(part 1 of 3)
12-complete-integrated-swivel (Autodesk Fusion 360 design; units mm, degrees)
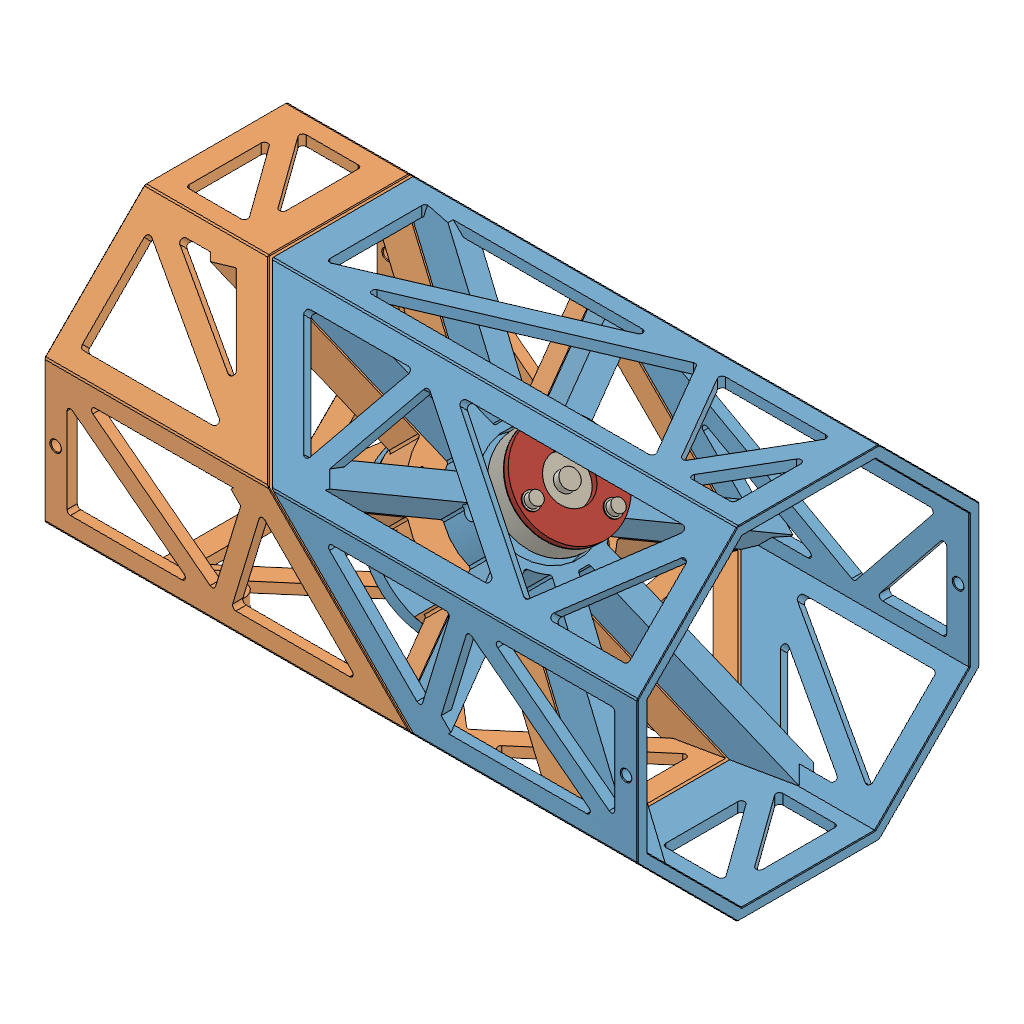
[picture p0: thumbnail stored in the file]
part number: 2026-11-02-20-17-55-344
part number: 2026-11-02-20-17-59-218
part number: 2026-11-02-20-17-59-224
part number: 2026-11-02-20-19-00-695
part number: 2026-11-02-20-19-03-009
part number: 2026-11-02-20-19-04-949
part number: 2026-11-02-20-19-06-912
part number: 2026-11-02-20-19-11-903
part number: 2026-11-02-20-19-12-666
part number: 2026-11-02-20-19-12-978
part number: 2026-11-02-20-19-13-740
part number: 2026-11-02-20-19-14-532
part number: 2026-11-02-20-19-15-361
part number: 2026-11-02-20-19-17-468
part number: 2026-11-02-20-19-19-583
part number: 2026-11-02-20-19-25-638
part number: 2026-11-02-20-19-39-091
parameter "bodyWidth" = 150 comment "Regular octagon across flats; corner diameter is larger."
parameter "bodyLength" = 260 comment "Overall straight length of the shared master blank."
parameter "splitAngle" = 45 comment "Keep this lesson angle at45 degrees."
parameter "faceGap" = 1 comment "Gap between the two printed joint faces."
parameter "wall" = 4.5 comment "Integrated shell and side brace radial thickness."
parameter "faceHalfWidth" = 31.066 (= "bodyWidth * ( sqrt(2) - 1 ) / 2") comment "Half-width of each outer planar facet."
parameter "memberWidth" = 8 comment "Nominal brace and corner chord width in a facet."
parameter "nodeHalfWidth" = 27.066 (= "faceHalfWidth - memberWidth / 2") comment "Chord centerlines measured from facet center."
parameter "jointNodeQ" = 7 comment "First truss skeleton row from the center joint plane."
parameter "endRim" = 10 comment "Uncut axial rim at each distant end."
parameter "endNodeX" = 124 (= "bodyLength / 2 - endRim + memberWidth / 2") comment "Last skeleton row before aperture inset."
parameter "apertureRadius" = 1.5 comment "Rounded internal corners at triangular openings."
parameter "spokeWidth" = 10 comment "Width of each deep bearing bulkhead spoke."
parameter "spokeDepth" = 18 comment "Bulkhead depth normal to the diagonal joint face."
parameter "carrierOD" = 52 comment "Outside of integrated A front bearing carrier."
parameter "rearCarrierClearance" = 46 comment "Internal carrier relief above front bearing shoulder."
parameter "tubeCornerChamfer" = 0.5 comment "Exposed outside octagon corner bevel."
parameter "tubeRimChamfer" = 0.3 comment "End rim and print-contact edge relief."
parameter "cordStation" = 125 (= "bodyLength / 2 - endRim / 2") comment "Load-test cord port center measured along body X."
parameter "bearingOD" = 22 comment "608 measured outside diameter."
parameter "bearingID" = 8 comment "608 bore."
parameter "bearingWidth" = 7 comment "608 width."
parameter "seatAllowance" = 0.2 comment "Trial DIAMETRAL clearance; choose with printed coupon."
parameter "seatDiameter" = 22.2 (= "bearingOD + seatAllowance") comment "Measured fit controls this."
parameter "coreOD" = 44 comment "Bearing holder outer diameter."
parameter "raceRelief" = 19.5 comment "Outer-ring shoulder opening; verify seals."
parameter "frontSeatDepth" = 7.1 comment "0.1 mm outer-ring axial allowance."
parameter "rearSeatDepth" = 7.2 comment "0.2 mm outer-ring axial float."
parameter "shoulder" = 3 comment "Backing behind each bearing seat."
parameter "supportSpacer" = 12 comment "Purchased metal M3 spacer length."
parameter "supportCircle" = 34 comment "Three M3 support bolts."
parameter "supportSpacerOD" = 6 comment "Purchased spacer outside diameter."
parameter "capThickness" = 3 comment "Both printed outer-ring retaining caps."
parameter "m3Clearance" = 3.3 comment "M3 through holes."
parameter "m4Clearance" = 4.3 comment "M4 through holes."
parameter "qFront" = 0.5 (= "faceGap / 2") comment "Front bearing starts at A mating face."
parameter "qFrontBack" = 10.6 (= "qFront + frontSeatDepth + shoulder") comment "End of integrated A holder."
parameter "qRearBase" = 22.6 (= "qFrontBack + supportSpacer") comment "Start of removable rear holder."
parameter "qRearBearing" = 25.6 (= "qRearBase + shoulder") comment "Rear bearing inner end."
parameter "qRearEnd" = 32.8 (= "qRearBearing + rearSeatDepth") comment "Rear holder outer end."
parameter "bearingSpacing" = 25.1 (= "qRearBearing - qFront") comment "Derived support-center spacing, not a bearing rating."
parameter "mountOD" = 76 comment "B mount and F flange outside diameter."
parameter "mountCircle" = 64 comment "Four M4 attachment holes."
parameter "mountOpening" = 50.3 comment "B through opening."
parameter "hubFace" = -23 comment "Metal hub flat mounting face."
parameter "adapterThickness" = 6 comment "F flange and metal compression sleeve length."
parameter "pilotDiameter" = 50 comment "F shallow centering pilot."
parameter "pilotInside" = 34 comment "Clearance around metal hub."
parameter "pilotHeight" = 2 comment "Short pilot only."
parameter "hubHoleSpacing" = 16 comment "Metal Sonic hub square hole spacing."
parameter "sleeveOD" = 8 comment "M4 metal compression sleeves."
parameter "sleeveAllowance" = 0.2 comment "Trial DIAMETRAL sleeve clearance."
parameter "shaftClearance" = 8.5 comment "F clearance hole; not a bearing."
parameter "nutAF" = 7.2 comment "M4 nominal 7 AF nut trial pocket."
parameter "nutDepth" = 4 comment "Open front M4 nut pocket."
parameter "rootRadius" = 1 comment "Hub-to-wall blend."
parameter "entryChamfer" = 0.4 comment "Assembly lead-in."
parameter "bedRelief" = 0.3 comment "Bed-contact edge allowance."
parameter "driverPort" = 5 comment "Clearance for bare3 mm hex-key shafts; bulky bit holders do not fit."
parameter "accessPadWidth" = 12 comment "Reinforced access-port capsule width."
parameter "accessPadExtra" = 2 comment "Local inward reinforcement beyond nominal side wall."
sketch "01 Master Octagon" plane through (0, 0, 0) normal (1, 0, 0) x axis (0, 0, -1)
  line L1 (31.066, 75) -> (75, 31.066)
  line L2 (-31.066, 75) -> (31.066, 75)
  line L3 (-75, 31.066) -> (-31.066, 75)
  line L4 (-75, -31.066) -> (-75, 31.066)
  line L5 (-31.066, -75) -> (-75, -31.066)
  line L6 (31.066, -75) -> (-31.066, -75)
  line L7 (75, -31.066) -> (31.066, -75)
  line L8 (75, 31.066) -> (75, -31.066)
  point P1 (0, 0)
  point P10 (0, 0)
  point P3 (31.066, 75)
  point P8 (31.066, -75)
  coincident P1 P10
  horizontal L2
  dimension "d59" distance P3 P8 = 150 (= "bodyWidth")
extrude "Extrude1" new body sketch "01 Master Octagon" distance 260 (= "bodyLength")
work_plane "WorkPlane1" RotateAngle 45 (= "splitAngle") ExtraOffset 0
split "Split1"
offset_faces "OffsetFaces1" distance -0.5 (= "-faceGap / 2")
offset_faces "OffsetFaces2" distance -0.5 (= "-faceGap / 2")
component_from_bodies "Body->Comp1"
component_from_bodies "Body->Comp2"
shell "Shell1" innerThickness 4.5 (= "wall")
shell "Shell1" innerThickness 4.5 (= "wall")
work_plane "WorkPlane1" RotateAngle -90 ExtraOffset 0
work_plane "WorkPlane2" AlongDistance 75 (= "bodyWidth / 2") ExtraOffset 0
sketch "A Facet 0 Triangle 1" plane through (0, 75, 0) normal (0, 1, 0) x axis (1, 0, 0)
  line L1 (-65.1005, -27.066) -> (-65.1005, 27.066)
  line L2 (60.9665, 27.066) -> (-65.1005, -27.066)
  line L3 (-65.1005, 27.066) -> (60.9665, 27.066)
  line L4 (-61.1005, -20.9953) -> (-61.1005, 23.066)
  line L5 (41.513, 23.066) -> (-61.1005, -20.9953)
  line L6 (-61.1005, 23.066) -> (41.513, 23.066)
  point P1 (0, 0)
  point P2 (-65.1005, 27.066)
  point P3 (-65.1005, -27.066)
  point P4 (60.9665, 27.066)
  dimension "d72" distance P1 P2 = 65.1005 (= "Linear Dimension-2")
  dimension "d73" distance P1 P2 = 27.066 (= "Linear Dimension-3")
  dimension "d74" distance P1 P3 = 65.1005 (= "Linear Dimension-4")
  dimension "d75" distance P1 P3 = 27.066 (= "Linear Dimension-5")
  dimension "d76" distance P1 P4 = 60.9665 (= "Linear Dimension-6")
  dimension "d77" distance P1 P4 = 27.066 (= "Linear Dimension-7")
  dimension "d78" = -4 (= "-memberWidth / 2")
extrude "Extrude1" cut sketch "A Facet 0 Triangle 1" profile of L5 L6 L4 against normal blind 4.7 (magnitude of "-( wall + 0.2 mm )")
sketch "A Facet 0 Triangle 2" plane through (0, 75, 0) normal (0, 1, 0) x axis (1, 0, 0)
  line L1 (60.9665, 27.066) -> (-65.1005, -27.066)
  line L2 (92.4832, -27.066) -> (60.9665, 27.066)
  line L3 (-65.1005, -27.066) -> (92.4832, -27.066)
  line L4 (59.2912, 21.9935) -> (-45.647, -23.066)
  line L5 (85.5258, -23.066) -> (59.2912, 21.9935)
  line L6 (-45.647, -23.066) -> (85.5258, -23.066)
  point P1 (0, 0)
  point P2 (-65.1005, -27.066)
  point P3 (60.9665, 27.066)
  point P4 (92.4832, -27.066)
  dimension "d81" distance P1 P2 = 65.1005 (= "Linear Dimension-2")
  dimension "d82" distance P1 P2 = 27.066 (= "Linear Dimension-3")
  dimension "d83" distance P1 P3 = 60.9665 (= "Linear Dimension-4")
  dimension "d84" distance P1 P3 = 27.066 (= "Linear Dimension-5")
  dimension "d85" distance P1 P4 = 92.4832 (= "Linear Dimension-6")
  dimension "d86" distance P1 P4 = 27.066 (= "Linear Dimension-7")
  dimension "d87" = 4 (= "memberWidth / 2")
extrude "Extrude2" cut sketch "A Facet 0 Triangle 2" profile of L5 L6 L4 against normal blind 4.7 (magnitude of "-( wall + 0.2 mm )")
sketch "A Facet 0 Triangle 3" plane through (0, 75, 0) normal (0, 1, 0) x axis (1, 0, 0)
  line L1 (92.4832, -27.066) -> (60.9665, 27.066)
  line L2 (124, 27.066) -> (92.4832, -27.066)
  line L3 (60.9665, 27.066) -> (124, 27.066)
  line L4 (92.4832, -19.1161) -> (67.924, 23.066)
  line L5 (117.0425, 23.066) -> (92.4832, -19.1161)
  line L6 (67.924, 23.066) -> (117.0425, 23.066)
  point P1 (0, 0)
  point P2 (60.9665, 27.066)
  point P3 (92.4832, -27.066)
  point P4 (124, 27.066)
  dimension "d90" distance P1 P2 = 60.9665 (= "Linear Dimension-2")
  dimension "d91" distance P1 P2 = 27.066 (= "Linear Dimension-3")
  dimension "d92" distance P1 P3 = 92.4832 (= "Linear Dimension-4")
  dimension "d93" distance P1 P3 = 27.066 (= "Linear Dimension-5")
  dimension "d94" distance P1 P4 = 124 (= "Linear Dimension-6")
  dimension "d95" distance P1 P4 = 27.066 (= "Linear Dimension-7")
  dimension "d96" = -4 (= "-memberWidth / 2")
extrude "Extrude3" cut sketch "A Facet 0 Triangle 3" profile of L5 L6 L4 against normal blind 4.7 (magnitude of "-( wall + 0.2 mm )")
sketch "A Facet 0 Triangle 4" plane through (0, 75, 0) normal (0, 1, 0) x axis (1, 0, 0)
  line L1 (124, 27.066) -> (92.4832, -27.066)
  line L2 (124, -27.066) -> (124, 27.066)
  line L3 (92.4832, -27.066) -> (124, -27.066)
  line L4 (120, 12.2459) -> (99.4407, -23.066)
  line L5 (120, -23.066) -> (120, 12.2459)
  line L6 (99.4407, -23.066) -> (120, -23.066)
  point P1 (0, 0)
  point P2 (92.4832, -27.066)
  point P3 (124, 27.066)
  point P4 (124, -27.066)
  dimension "d99" distance P1 P2 = 92.4832 (= "Linear Dimension-2")
  dimension "d100" distance P1 P2 = 27.066 (= "Linear Dimension-3")
  dimension "d101" distance P1 P3 = 124 (= "Linear Dimension-4")
  dimension "d102" distance P1 P3 = 27.066 (= "Linear Dimension-5")
  dimension "d103" distance P1 P4 = 124 (= "Linear Dimension-6")
  dimension "d104" distance P1 P4 = 27.066 (= "Linear Dimension-7")
  dimension "d105" = 4 (= "memberWidth / 2")
extrude "Extrude4" cut sketch "A Facet 0 Triangle 4" profile of L5 L6 L4 against normal blind 4.7 (magnitude of "-( wall + 0.2 mm )")
fillet "Fillet1" radius 1.5 (= "apertureRadius")
work_plane "WorkPlane3" RotateAngle -45 ExtraOffset 0
work_plane "WorkPlane4" AlongDistance 75 (= "bodyWidth / 2") ExtraOffset 0
sketch "A Facet 45 Triangle 1" plane through (0, 53.033, 53.033) normal (0, 0.7071, 0.7071) x axis (1, 0, 0)
  line L1 (-23.9949, -27.066) -> (-62.2721, 27.066)
  line L2 (-0.1814, 27.066) -> (-23.9949, -27.066)
  line L3 (-62.2721, 27.066) -> (-0.1814, 27.066)
  line L4 (-24.81, -18.9852) -> (-54.5447, 23.066)
  line L5 (-6.311, 23.066) -> (-24.81, -18.9852)
  line L6 (-54.5447, 23.066) -> (-6.311, 23.066)
  point P1 (0, 0)
  point P2 (-62.2721, 27.066)
  point P3 (-23.9949, -27.066)
  point P4 (-0.1814, 27.066)
  dimension "d114" distance P1 P2 = 62.2721 (= "Linear Dimension-2")
  dimension "d115" distance P1 P2 = 27.066 (= "Linear Dimension-3")
  dimension "d116" distance P1 P3 = 23.9949 (= "Linear Dimension-4")
  dimension "d117" distance P1 P3 = 27.066 (= "Linear Dimension-5")
  dimension "d118" distance P1 P4 = 0.1814 (= "Linear Dimension-6")
  dimension "d119" distance P1 P4 = 27.066 (= "Linear Dimension-7")
  dimension "d120" = -4 (= "-memberWidth / 2")
extrude "Extrude5" cut sketch "A Facet 45 Triangle 1" profile of L5 L6 L4 against normal blind 4.7 (magnitude of "-( wall + 0.2 mm )")
sketch "A Facet 45 Triangle 2" plane through (0, 53.033, 53.033) normal (0, 0.7071, 0.7071) x axis (1, 0, 0)
  line L1 (-0.1814, 27.066) -> (-23.9949, -27.066)
  line L2 (74.6684, -27.066) -> (-0.1814, 27.066)
  line L3 (-23.9949, -27.066) -> (74.6684, -27.066)
  line L4 (1.4863, 20.9235) -> (-17.8653, -23.066)
  line L5 (62.3117, -23.066) -> (1.4863, 20.9235)
  line L6 (-17.8653, -23.066) -> (62.3117, -23.066)
  point P1 (0, 0)
  point P2 (-23.9949, -27.066)
  point P3 (-0.1814, 27.066)
  point P4 (74.6684, -27.066)
  dimension "d123" distance P1 P2 = 23.9949 (= "Linear Dimension-2")
  dimension "d124" distance P1 P2 = 27.066 (= "Linear Dimension-3")
  dimension "d125" distance P1 P3 = 0.1814 (= "Linear Dimension-4")
  dimension "d126" distance P1 P3 = 27.066 (= "Linear Dimension-5")
  dimension "d127" distance P1 P4 = 74.6684 (= "Linear Dimension-6")
  dimension "d128" distance P1 P4 = 27.066 (= "Linear Dimension-7")
  dimension "d129" = 4 (= "memberWidth / 2")
extrude "Extrude6" cut sketch "A Facet 45 Triangle 2" profile of L5 L6 L4 against normal blind 4.7 (magnitude of "-( wall + 0.2 mm )")
sketch "A Facet 45 Triangle 3" plane through (0, 53.033, 53.033) normal (0, 0.7071, 0.7071) x axis (1, 0, 0)
  line L1 (74.6684, -27.066) -> (-0.1814, 27.066)
  line L2 (124, 27.066) -> (74.6684, -27.066)
  line L3 (-0.1814, 27.066) -> (124, 27.066)
  line L4 (74.1179, -21.7315) -> (12.1753, 23.066)
  line L5 (114.9429, 23.066) -> (74.1179, -21.7315)
  line L6 (12.1753, 23.066) -> (114.9429, 23.066)
  point P1 (0, 0)
  point P2 (-0.1814, 27.066)
  point P3 (74.6684, -27.066)
  point P4 (124, 27.066)
  dimension "d132" distance P1 P2 = 0.1814 (= "Linear Dimension-2")
  dimension "d133" distance P1 P2 = 27.066 (= "Linear Dimension-3")
  dimension "d134" distance P1 P3 = 74.6684 (= "Linear Dimension-4")
  dimension "d135" distance P1 P3 = 27.066 (= "Linear Dimension-5")
  dimension "d136" distance P1 P4 = 124 (= "Linear Dimension-6")
  dimension "d137" distance P1 P4 = 27.066 (= "Linear Dimension-7")
  dimension "d138" = -4 (= "-memberWidth / 2")
extrude "Extrude7" cut sketch "A Facet 45 Triangle 3" profile of L5 L6 L4 against normal blind 4.7 (magnitude of "-( wall + 0.2 mm )")
sketch "A Facet 45 Triangle 4" plane through (0, 53.033, 53.033) normal (0, 0.7071, 0.7071) x axis (1, 0, 0)
  line L1 (124, 27.066) -> (74.6684, -27.066)
  line L2 (124, -27.066) -> (124, 27.066)
  line L3 (74.6684, -27.066) -> (124, -27.066)
  line L4 (120, 16.7383) -> (83.7255, -23.066)
  line L5 (120, -23.066) -> (120, 16.7383)
  line L6 (83.7255, -23.066) -> (120, -23.066)
  point P1 (0, 0)
  point P2 (74.6684, -27.066)
  point P3 (124, 27.066)
  point P4 (124, -27.066)
  dimension "d141" distance P1 P2 = 74.6684 (= "Linear Dimension-2")
  dimension "d142" distance P1 P2 = 27.066 (= "Linear Dimension-3")
  dimension "d143" distance P1 P3 = 124 (= "Linear Dimension-4")
  dimension "d144" distance P1 P3 = 27.066 (= "Linear Dimension-5")
  dimension "d145" distance P1 P4 = 124 (= "Linear Dimension-6")
  dimension "d146" distance P1 P4 = 27.066 (= "Linear Dimension-7")
  dimension "d147" = 4 (= "memberWidth / 2")
extrude "Extrude8" cut sketch "A Facet 45 Triangle 4" profile of L5 L6 L4 against normal blind 4.7 (magnitude of "-( wall + 0.2 mm )")
fillet "Fillet2" radius 1.5 (= "apertureRadius")
work_plane "WorkPlane5" RotateAngle 0 ExtraOffset 0
work_plane "WorkPlane6" AlongDistance 75 (= "bodyWidth / 2") ExtraOffset 0
sketch "A Facet 90 Triangle 1" plane through (0, 0, 75) normal (0, 0, 1) x axis (1, 0, 0)
  line L1 (36.9655, -27.066) -> (-17.1665, 27.066)
  line L2 (53.4167, 27.066) -> (36.9655, -27.066)
  line L3 (-17.1665, 27.066) -> (53.4167, 27.066)
  line L4 (35.0777, -19.5214) -> (-7.5097, 23.066)
  line L5 (48.0205, 23.066) -> (35.0777, -19.5214)
  line L6 (-7.5097, 23.066) -> (48.0205, 23.066)
  point P1 (0, 0)
  point P2 (-17.1665, 27.066)
  point P3 (36.9655, -27.066)
  point P4 (53.4167, 27.066)
  dimension "d156" distance P1 P2 = 17.1665 (= "Linear Dimension-2")
  dimension "d157" distance P1 P2 = 27.066 (= "Linear Dimension-3")
  dimension "d158" distance P1 P3 = 36.9655 (= "Linear Dimension-4")
  dimension "d159" distance P1 P3 = 27.066 (= "Linear Dimension-5")
  dimension "d160" distance P1 P4 = 53.4167 (= "Linear Dimension-6")
  dimension "d161" distance P1 P4 = 27.066 (= "Linear Dimension-7")
  dimension "d162" = -4 (= "-memberWidth / 2")
extrude "Extrude9" cut sketch "A Facet 90 Triangle 1" profile of L5 L6 L4 against normal blind 4.7 (magnitude of "-( wall + 0.2 mm )")
sketch "A Facet 90 Triangle 2" plane through (0, 0, 75) normal (0, 0, 1) x axis (1, 0, 0)
  line L1 (53.4167, 27.066) -> (36.9655, -27.066)
  line L2 (124, -27.066) -> (53.4167, 27.066)
  line L3 (36.9655, -27.066) -> (124, -27.066)
  line L4 (55.5648, 20.3777) -> (42.3618, -23.066)
  line L5 (112.2115, -23.066) -> (55.5648, 20.3777)
  line L6 (42.3618, -23.066) -> (112.2115, -23.066)
  point P1 (0, 0)
  point P2 (36.9655, -27.066)
  point P3 (53.4167, 27.066)
  point P4 (124, -27.066)
  dimension "d165" distance P1 P2 = 36.9655 (= "Linear Dimension-2")
  dimension "d166" distance P1 P2 = 27.066 (= "Linear Dimension-3")
  dimension "d167" distance P1 P3 = 53.4167 (= "Linear Dimension-4")
  dimension "d168" distance P1 P3 = 27.066 (= "Linear Dimension-5")
  dimension "d169" distance P1 P4 = 124 (= "Linear Dimension-6")
  dimension "d170" distance P1 P4 = 27.066 (= "Linear Dimension-7")
  dimension "d171" = 4 (= "memberWidth / 2")
extrude "Extrude10" cut sketch "A Facet 90 Triangle 2" profile of L5 L6 L4 against normal blind 4.7 (magnitude of "-( wall + 0.2 mm )")
sketch "A Facet 90 Triangle 3" plane through (0, 0, 75) normal (0, 0, 1) x axis (1, 0, 0)
  line L1 (124, -27.066) -> (53.4167, 27.066)
  line L2 (124, 27.066) -> (124, -27.066)
  line L3 (53.4167, 27.066) -> (124, 27.066)
  line L4 (120, -18.9574) -> (65.2053, 23.066)
  line L5 (120, 23.066) -> (120, -18.9574)
  line L6 (65.2053, 23.066) -> (120, 23.066)
  point P1 (0, 0)
  point P2 (53.4167, 27.066)
  point P3 (124, -27.066)
  point P4 (124, 27.066)
  dimension "d174" distance P1 P2 = 53.4167 (= "Linear Dimension-2")
  dimension "d175" distance P1 P2 = 27.066 (= "Linear Dimension-3")
  dimension "d176" distance P1 P3 = 124 (= "Linear Dimension-4")
  dimension "d177" distance P1 P3 = 27.066 (= "Linear Dimension-5")
  dimension "d178" distance P1 P4 = 124 (= "Linear Dimension-6")
  dimension "d179" distance P1 P4 = 27.066 (= "Linear Dimension-7")
  dimension "d180" = -4 (= "-memberWidth / 2")
extrude "Extrude11" cut sketch "A Facet 90 Triangle 3" profile of L5 L6 L4 against normal blind 4.7 (magnitude of "-( wall + 0.2 mm )")
fillet "Fillet3" radius 1.5 (= "apertureRadius")
work_plane "WorkPlane7" RotateAngle 45 ExtraOffset 0
work_plane "WorkPlane8" AlongDistance 75 (= "bodyWidth / 2") ExtraOffset 0
sketch "A Facet 135 Triangle 1" plane through (0, -53.033, 53.033) normal (0, -0.7071, 0.7071) x axis (1, 0, 0)
  line L1 (82.0711, -27.066) -> (43.7939, 27.066)
  line L2 (124, 27.066) -> (82.0711, -27.066)
  line L3 (43.7939, 27.066) -> (124, 27.066)
  line L4 (82.2175, -20.3449) -> (51.5213, 23.066)
  line L5 (115.8422, 23.066) -> (82.2175, -20.3449)
  line L6 (51.5213, 23.066) -> (115.8422, 23.066)
  point P1 (0, 0)
  point P2 (43.7939, 27.066)
  point P3 (82.0711, -27.066)
  point P4 (124, 27.066)
  dimension "d189" distance P1 P2 = 43.7939 (= "Linear Dimension-2")
  dimension "d190" distance P1 P2 = 27.066 (= "Linear Dimension-3")
  dimension "d191" distance P1 P3 = 82.0711 (= "Linear Dimension-4")
  dimension "d192" distance P1 P3 = 27.066 (= "Linear Dimension-5")
  dimension "d193" distance P1 P4 = 124 (= "Linear Dimension-6")
  dimension "d194" distance P1 P4 = 27.066 (= "Linear Dimension-7")
  dimension "d195" = -4 (= "-memberWidth / 2")
extrude "Extrude12" cut sketch "A Facet 135 Triangle 1" profile of L5 L6 L4 against normal blind 4.7 (magnitude of "-( wall + 0.2 mm )")
sketch "A Facet 135 Triangle 2" plane through (0, -53.033, 53.033) normal (0, -0.7071, 0.7071) x axis (1, 0, 0)
  line L1 (124, 27.066) -> (82.0711, -27.066)
  line L2 (124, -27.066) -> (124, 27.066)
  line L3 (82.0711, -27.066) -> (124, -27.066)
  line L4 (120, 15.3697) -> (90.2289, -23.066)
  line L5 (120, -23.066) -> (120, 15.3697)
  line L6 (90.2289, -23.066) -> (120, -23.066)
  point P1 (0, 0)
  point P2 (82.0711, -27.066)
  point P3 (124, 27.066)
  point P4 (124, -27.066)
  dimension "d198" distance P1 P2 = 82.0711 (= "Linear Dimension-2")
  dimension "d199" distance P1 P2 = 27.066 (= "Linear Dimension-3")
  dimension "d200" distance P1 P3 = 124 (= "Linear Dimension-4")
  dimension "d201" distance P1 P3 = 27.066 (= "Linear Dimension-5")
  dimension "d202" distance P1 P4 = 124 (= "Linear Dimension-6")
  dimension "d203" distance P1 P4 = 27.066 (= "Linear Dimension-7")
  dimension "d204" = 4 (= "memberWidth / 2")
extrude "Extrude13" cut sketch "A Facet 135 Triangle 2" profile of L5 L6 L4 against normal blind 4.7 (magnitude of "-( wall + 0.2 mm )")
fillet "Fillet4" radius 1.5 (= "apertureRadius")
work_plane "WorkPlane9" RotateAngle 90 ExtraOffset 0
work_plane "WorkPlane10" AlongDistance 75 (= "bodyWidth / 2") ExtraOffset 0
sketch "A Facet 180 Triangle 1" plane through (0, -75, 0) normal (0, -1, 0) x axis (-1, 0, 0)
  line L1 (-84.8995, 27.066) -> (-84.8995, -27.066)
  line L2 (-124, -27.066) -> (-84.8995, 27.066)
  line L3 (-84.8995, -27.066) -> (-124, -27.066)
  line L4 (-88.8995, 14.697) -> (-88.8995, -23.066)
  line L5 (-116.1764, -23.066) -> (-88.8995, 14.697)
  line L6 (-88.8995, -23.066) -> (-116.1764, -23.066)
  point P1 (0, 0)
  point P2 (-84.8995, -27.066)
  point P3 (-84.8995, 27.066)
  point P4 (-124, -27.066)
  dimension "d213" distance P1 P2 = 84.8995 (= "Linear Dimension-2")
  dimension "d214" distance P1 P2 = 27.066 (= "Linear Dimension-3")
  dimension "d215" distance P1 P3 = 84.8995 (= "Linear Dimension-4")
  dimension "d216" distance P1 P3 = 27.066 (= "Linear Dimension-5")
  dimension "d217" distance P1 P4 = 124 (= "Linear Dimension-6")
  dimension "d218" distance P1 P4 = 27.066 (= "Linear Dimension-7")
  dimension "d219" = -4 (= "-memberWidth / 2")
extrude "Extrude14" cut sketch "A Facet 180 Triangle 1" profile of L5 L6 L4 against normal blind 4.7 (magnitude of "-( wall + 0.2 mm )")
sketch "A Facet 180 Triangle 2" plane through (0, -75, 0) normal (0, -1, 0) x axis (-1, 0, 0)
  line L1 (-124, -27.066) -> (-84.8995, 27.066)
  line L2 (-124, 27.066) -> (-124, -27.066)
  line L3 (-84.8995, 27.066) -> (-124, 27.066)
  line L4 (-120, -14.697) -> (-92.7231, 23.066)
  line L5 (-120, 23.066) -> (-120, -14.697)
  line L6 (-92.7231, 23.066) -> (-120, 23.066)
  point P1 (0, 0)
  point P2 (-84.8995, 27.066)
  point P3 (-124, -27.066)
  point P4 (-124, 27.066)
  dimension "d222" distance P1 P2 = 84.8995 (= "Linear Dimension-2")
  dimension "d223" distance P1 P2 = 27.066 (= "Linear Dimension-3")
  dimension "d224" distance P1 P3 = 124 (= "Linear Dimension-4")
  dimension "d225" distance P1 P3 = 27.066 (= "Linear Dimension-5")
  dimension "d226" distance P1 P4 = 124 (= "Linear Dimension-6")
  dimension "d227" distance P1 P4 = 27.066 (= "Linear Dimension-7")
  dimension "d228" = 4 (= "memberWidth / 2")
extrude "Extrude15" cut sketch "A Facet 180 Triangle 2" profile of L5 L6 L4 against normal blind 4.7 (magnitude of "-( wall + 0.2 mm )")
fillet "Fillet5" radius 1.5 (= "apertureRadius")
work_plane "WorkPlane11" RotateAngle 135 ExtraOffset 0
work_plane "WorkPlane12" AlongDistance 75 (= "bodyWidth / 2") ExtraOffset 0
sketch "A Facet 225 Triangle 1" plane through (0, -53.033, -53.033) normal (0, -0.7071, -0.7071) x axis (1, 0, 0)
  line L1 (43.7939, -27.066) -> (82.0711, 27.066)
  line L2 (124, 27.066) -> (43.7939, -27.066)
  line L3 (82.0711, 27.066) -> (124, 27.066)
  line L4 (59.6927, -11.51) -> (84.1416, 23.066)
  line L5 (110.9231, 23.066) -> (59.6927, -11.51)
  line L6 (84.1416, 23.066) -> (110.9231, 23.066)
  point P1 (0, 0)
  point P2 (82.0711, 27.066)
  point P3 (43.7939, -27.066)
  point P4 (124, 27.066)
  dimension "d237" distance P1 P2 = 82.0711 (= "Linear Dimension-2")
  dimension "d238" distance P1 P2 = 27.066 (= "Linear Dimension-3")
  dimension "d239" distance P1 P3 = 43.7939 (= "Linear Dimension-4")
  dimension "d240" distance P1 P3 = 27.066 (= "Linear Dimension-5")
  dimension "d241" distance P1 P4 = 124 (= "Linear Dimension-6")
  dimension "d242" distance P1 P4 = 27.066 (= "Linear Dimension-7")
  dimension "d243" = -4 (= "-memberWidth / 2")
extrude "Extrude16" cut sketch "A Facet 225 Triangle 1" profile of L5 L6 L4 against normal blind 4.7 (magnitude of "-( wall + 0.2 mm )")
sketch "A Facet 225 Triangle 2" plane through (0, -53.033, -53.033) normal (0, -0.7071, -0.7071) x axis (1, 0, 0)
  line L1 (124, 27.066) -> (43.7939, -27.066)
  line L2 (124, -27.066) -> (124, 27.066)
  line L3 (43.7939, -27.066) -> (124, -27.066)
  line L4 (120, 19.5406) -> (56.8709, -23.066)
  line L5 (120, -23.066) -> (120, 19.5406)
  line L6 (56.8709, -23.066) -> (120, -23.066)
  point P1 (0, 0)
  point P2 (43.7939, -27.066)
  point P3 (124, 27.066)
  point P4 (124, -27.066)
  dimension "d246" distance P1 P2 = 43.7939 (= "Linear Dimension-2")
  dimension "d247" distance P1 P2 = 27.066 (= "Linear Dimension-3")
  dimension "d248" distance P1 P3 = 124 (= "Linear Dimension-4")
  dimension "d249" distance P1 P3 = 27.066 (= "Linear Dimension-5")
  dimension "d250" distance P1 P4 = 124 (= "Linear Dimension-6")
  dimension "d251" distance P1 P4 = 27.066 (= "Linear Dimension-7")
  dimension "d252" = 4 (= "memberWidth / 2")
extrude "Extrude17" cut sketch "A Facet 225 Triangle 2" profile of L5 L6 L4 against normal blind 4.7 (magnitude of "-( wall + 0.2 mm )")
fillet "Fillet6" radius 1.5 (= "apertureRadius")
work_plane "WorkPlane13" RotateAngle 180 ExtraOffset 0
work_plane "WorkPlane14" AlongDistance 75 (= "bodyWidth / 2") ExtraOffset 0
sketch "A Facet 270 Triangle 1" plane through (0, 0, -75) normal (0, 0, -1) x axis (-1, 0, 0)
  line L1 (17.1665, 27.066) -> (-36.9655, -27.066)
  line L2 (-80.4828, -27.066) -> (17.1665, 27.066)
  line L3 (-36.9655, -27.066) -> (-80.4828, -27.066)
  line L4 (-5.7896, 9.7668) -> (-38.6224, -23.066)
  line L5 (-65.0169, -23.066) -> (-5.7896, 9.7668)
  line L6 (-38.6224, -23.066) -> (-65.0169, -23.066)
  point P1 (0, 0)
  point P2 (-36.9655, -27.066)
  point P3 (17.1665, 27.066)
  point P4 (-80.4828, -27.066)
  dimension "d261" distance P1 P2 = 36.9655 (= "Linear Dimension-2")
  dimension "d262" distance P1 P2 = 27.066 (= "Linear Dimension-3")
  dimension "d263" distance P1 P3 = 17.1665 (= "Linear Dimension-4")
  dimension "d264" distance P1 P3 = 27.066 (= "Linear Dimension-5")
  dimension "d265" distance P1 P4 = 80.4828 (= "Linear Dimension-6")
  dimension "d266" distance P1 P4 = 27.066 (= "Linear Dimension-7")
  dimension "d267" = -4 (= "-memberWidth / 2")
extrude "Extrude18" cut sketch "A Facet 270 Triangle 1" profile of L5 L6 L4 against normal blind 4.7 (magnitude of "-( wall + 0.2 mm )")
sketch "A Facet 270 Triangle 2" plane through (0, 0, -75) normal (0, 0, -1) x axis (-1, 0, 0)
  line L1 (-80.4828, -27.066) -> (17.1665, 27.066)
  line L2 (-124, 27.066) -> (-80.4828, -27.066)
  line L3 (17.1665, 27.066) -> (-124, 27.066)
  line L4 (-79.4759, -21.9343) -> (1.7007, 23.066)
  line L5 (-115.6521, 23.066) -> (-79.4759, -21.9343)
  line L6 (1.7007, 23.066) -> (-115.6521, 23.066)
  point P1 (0, 0)
  point P2 (17.1665, 27.066)
  point P3 (-80.4828, -27.066)
  point P4 (-124, 27.066)
  dimension "d270" distance P1 P2 = 17.1665 (= "Linear Dimension-2")
  dimension "d271" distance P1 P2 = 27.066 (= "Linear Dimension-3")
  dimension "d272" distance P1 P3 = 80.4828 (= "Linear Dimension-4")
  dimension "d273" distance P1 P3 = 27.066 (= "Linear Dimension-5")
  dimension "d274" distance P1 P4 = 124 (= "Linear Dimension-6")
  dimension "d275" distance P1 P4 = 27.066 (= "Linear Dimension-7")
  dimension "d276" = 4 (= "memberWidth / 2")
extrude "Extrude19" cut sketch "A Facet 270 Triangle 2" profile of L5 L6 L4 against normal blind 4.7 (magnitude of "-( wall + 0.2 mm )")
sketch "A Facet 270 Triangle 3" plane through (0, 0, -75) normal (0, 0, -1) x axis (-1, 0, 0)
  line L1 (-124, 27.066) -> (-80.4828, -27.066)
  line L2 (-124, -27.066) -> (-124, 27.066)
  line L3 (-80.4828, -27.066) -> (-124, -27.066)
  line L4 (-120, 15.7062) -> (-88.8307, -23.066)
  line L5 (-120, -23.066) -> (-120, 15.7062)
  line L6 (-88.8307, -23.066) -> (-120, -23.066)
  point P1 (0, 0)
  point P2 (-80.4828, -27.066)
  point P3 (-124, 27.066)
  point P4 (-124, -27.066)
  dimension "d279" distance P1 P2 = 80.4828 (= "Linear Dimension-2")
  dimension "d280" distance P1 P2 = 27.066 (= "Linear Dimension-3")
  dimension "d281" distance P1 P3 = 124 (= "Linear Dimension-4")
  dimension "d282" distance P1 P3 = 27.066 (= "Linear Dimension-5")
  dimension "d283" distance P1 P4 = 124 (= "Linear Dimension-6")
  dimension "d284" distance P1 P4 = 27.066 (= "Linear Dimension-7")
  dimension "d285" = -4 (= "-memberWidth / 2")
extrude "Extrude20" cut sketch "A Facet 270 Triangle 3" profile of L5 L6 L4 against normal blind 4.7 (magnitude of "-( wall + 0.2 mm )")
fillet "Fillet7" radius 1.5 (= "apertureRadius")
work_plane "WorkPlane15" RotateAngle 225 ExtraOffset 0
work_plane "WorkPlane16" AlongDistance 75 (= "bodyWidth / 2") ExtraOffset 0
sketch "A Facet 315 Triangle 1" plane through (0, 53.033, -53.033) normal (0, 0.7071, -0.7071) x axis (1, 0, 0)
  line L1 (-62.2721, -27.066) -> (-23.9949, 27.066)
  line L2 (25.3367, 27.066) -> (-62.2721, -27.066)
  line L3 (-23.9949, 27.066) -> (25.3367, 27.066)
  line L4 (-47.6674, -13.34) -> (-21.9244, 23.066)
  line L5 (11.2532, 23.066) -> (-47.6674, -13.34)
  line L6 (-21.9244, 23.066) -> (11.2532, 23.066)
  point P1 (0, 0)
  point P2 (-23.9949, 27.066)
  point P3 (-62.2721, -27.066)
  point P4 (25.3367, 27.066)
  dimension "d294" distance P1 P2 = 23.9949 (= "Linear Dimension-2")
  dimension "d295" distance P1 P2 = 27.066 (= "Linear Dimension-3")
  dimension "d296" distance P1 P3 = 62.2721 (= "Linear Dimension-4")
  dimension "d297" distance P1 P3 = 27.066 (= "Linear Dimension-5")
  dimension "d298" distance P1 P4 = 25.3367 (= "Linear Dimension-6")
  dimension "d299" distance P1 P4 = 27.066 (= "Linear Dimension-7")
  dimension "d300" = -4 (= "-memberWidth / 2")
extrude "Extrude21" cut sketch "A Facet 315 Triangle 1" profile of L5 L6 L4 against normal blind 4.7 (magnitude of "-( wall + 0.2 mm )")
sketch "A Facet 315 Triangle 2" plane through (0, 53.033, -53.033) normal (0, 0.7071, -0.7071) x axis (1, 0, 0)
  line L1 (25.3367, 27.066) -> (-62.2721, -27.066)
  line L2 (61.9093, -27.066) -> (25.3367, 27.066)
  line L3 (-62.2721, -27.066) -> (61.9093, -27.066)
  line L4 (24.1722, 21.6445) -> (-48.1886, -23.066)
  line L5 (54.3795, -23.066) -> (24.1722, 21.6445)
  line L6 (-48.1886, -23.066) -> (54.3795, -23.066)
  point P1 (0, 0)
  point P2 (-62.2721, -27.066)
  point P3 (25.3367, 27.066)
  point P4 (61.9093, -27.066)
  dimension "d303" distance P1 P2 = 62.2721 (= "Linear Dimension-2")
  dimension "d304" distance P1 P2 = 27.066 (= "Linear Dimension-3")
  dimension "d305" distance P1 P3 = 25.3367 (= "Linear Dimension-4")
  dimension "d306" distance P1 P3 = 27.066 (= "Linear Dimension-5")
  dimension "d307" distance P1 P4 = 61.9093 (= "Linear Dimension-6")
  dimension "d308" distance P1 P4 = 27.066 (= "Linear Dimension-7")
  dimension "d309" = 4 (= "memberWidth / 2")
extrude "Extrude22" cut sketch "A Facet 315 Triangle 2" profile of L5 L6 L4 against normal blind 4.7 (magnitude of "-( wall + 0.2 mm )")
sketch "A Facet 315 Triangle 3" plane through (0, 53.033, -53.033) normal (0, 0.7071, -0.7071) x axis (1, 0, 0)
  line L1 (61.9093, -27.066) -> (25.3367, 27.066)
  line L2 (124, 27.066) -> (61.9093, -27.066)
  line L3 (25.3367, 27.066) -> (124, 27.066)
  line L4 (62.6909, -21.0779) -> (32.8665, 23.066)
  line L5 (113.325, 23.066) -> (62.6909, -21.0779)
  line L6 (32.8665, 23.066) -> (113.325, 23.066)
  point P1 (0, 0)
  point P2 (25.3367, 27.066)
  point P3 (61.9093, -27.066)
  point P4 (124, 27.066)
  dimension "d312" distance P1 P2 = 25.3367 (= "Linear Dimension-2")
  dimension "d313" distance P1 P2 = 27.066 (= "Linear Dimension-3")
  dimension "d314" distance P1 P3 = 61.9093 (= "Linear Dimension-4")
  dimension "d315" distance P1 P3 = 27.066 (= "Linear Dimension-5")
  dimension "d316" distance P1 P4 = 124 (= "Linear Dimension-6")
  dimension "d317" distance P1 P4 = 27.066 (= "Linear Dimension-7")
  dimension "d318" = -4 (= "-memberWidth / 2")
extrude "Extrude23" cut sketch "A Facet 315 Triangle 3" profile of L5 L6 L4 against normal blind 4.7 (magnitude of "-( wall + 0.2 mm )")
sketch "A Facet 315 Triangle 4" plane through (0, 53.033, -53.033) normal (0, 0.7071, -0.7071) x axis (1, 0, 0)
  line L1 (124, 27.066) -> (61.9093, -27.066)
  line L2 (124, -27.066) -> (124, 27.066)
  line L3 (61.9093, -27.066) -> (124, -27.066)
  line L4 (120, 18.272) -> (72.5843, -23.066)
  line L5 (120, -23.066) -> (120, 18.272)
  line L6 (72.5843, -23.066) -> (120, -23.066)
  point P1 (0, 0)
  point P2 (61.9093, -27.066)
  point P3 (124, 27.066)
  point P4 (124, -27.066)
  dimension "d321" distance P1 P2 = 61.9093 (= "Linear Dimension-2")
  dimension "d322" distance P1 P2 = 27.066 (= "Linear Dimension-3")
  dimension "d323" distance P1 P3 = 124 (= "Linear Dimension-4")
  dimension "d324" distance P1 P3 = 27.066 (= "Linear Dimension-5")
  dimension "d325" distance P1 P4 = 124 (= "Linear Dimension-6")
  dimension "d326" distance P1 P4 = 27.066 (= "Linear Dimension-7")
  dimension "d327" = 4 (= "memberWidth / 2")
extrude "Extrude24" cut sketch "A Facet 315 Triangle 4" profile of L5 L6 L4 against normal blind 4.7 (magnitude of "-( wall + 0.2 mm )")
fillet "Fillet8" radius 1.5 (= "apertureRadius")
work_plane "WorkPlane1" RotateAngle -90 ExtraOffset 0
work_plane "WorkPlane2" AlongDistance 75 (= "bodyWidth / 2") ExtraOffset 0
sketch "B Facet 0 Triangle 1" plane through (0, 75, 0) normal (0, 1, 0) x axis (1, 0, 0)
  line L1 (-84.8995, -27.066) -> (-84.8995, 27.066)
  line L2 (-124, 27.066) -> (-84.8995, -27.066)
  line L3 (-84.8995, 27.066) -> (-124, 27.066)
  line L4 (-88.8995, -14.697) -> (-88.8995, 23.066)
  line L5 (-116.1764, 23.066) -> (-88.8995, -14.697)
  line L6 (-88.8995, 23.066) -> (-116.1764, 23.066)
  point P1 (0, 0)
  point P2 (-84.8995, 27.066)
  point P3 (-84.8995, -27.066)
  point P4 (-124, 27.066)
  dimension "d336" distance P1 P2 = 84.8995 (= "Linear Dimension-2")
  dimension "d337" distance P1 P2 = 27.066 (= "Linear Dimension-3")
  dimension "d338" distance P1 P3 = 84.8995 (= "Linear Dimension-4")
  dimension "d339" distance P1 P3 = 27.066 (= "Linear Dimension-5")
  dimension "d340" distance P1 P4 = 124 (= "Linear Dimension-6")
  dimension "d341" distance P1 P4 = 27.066 (= "Linear Dimension-7")
  dimension "d342" = 4 (= "memberWidth / 2")
extrude "Extrude1" cut sketch "B Facet 0 Triangle 1" profile of L5 L6 L4 against normal blind 4.7 (magnitude of "-( wall + 0.2 mm )")
sketch "B Facet 0 Triangle 2" plane through (0, 75, 0) normal (0, 1, 0) x axis (1, 0, 0)
  line L1 (-124, 27.066) -> (-84.8995, -27.066)
  line L2 (-124, -27.066) -> (-124, 27.066)
  line L3 (-84.8995, -27.066) -> (-124, -27.066)
  line L4 (-120, 14.697) -> (-92.7231, -23.066)
  line L5 (-120, -23.066) -> (-120, 14.697)
  line L6 (-92.7231, -23.066) -> (-120, -23.066)
  point P1 (0, 0)
  point P2 (-84.8995, -27.066)
  point P3 (-124, 27.066)
  point P4 (-124, -27.066)
  dimension "d345" distance P1 P2 = 84.8995 (= "Linear Dimension-2")
  dimension "d346" distance P1 P2 = 27.066 (= "Linear Dimension-3")
  dimension "d347" distance P1 P3 = 124 (= "Linear Dimension-4")
  dimension "d348" distance P1 P3 = 27.066 (= "Linear Dimension-5")
  dimension "d349" distance P1 P4 = 124 (= "Linear Dimension-6")
  dimension "d350" distance P1 P4 = 27.066 (= "Linear Dimension-7")
  dimension "d351" = -4 (= "-memberWidth / 2")
extrude "Extrude2" cut sketch "B Facet 0 Triangle 2" profile of L5 L6 L4 against normal blind 4.7 (magnitude of "-( wall + 0.2 mm )")
fillet "Fillet1" radius 1.5 (= "apertureRadius")
work_plane "WorkPlane3" RotateAngle -45 ExtraOffset 0
work_plane "WorkPlane4" AlongDistance 75 (= "bodyWidth / 2") ExtraOffset 0
sketch "B Facet 45 Triangle 1" plane through (0, 53.033, 53.033) normal (0, 0.7071, 0.7071) x axis (1, 0, 0)
  line L1 (-43.7939, -27.066) -> (-82.0711, 27.066)
  line L2 (-124, 27.066) -> (-43.7939, -27.066)
  line L3 (-82.0711, 27.066) -> (-124, 27.066)
  line L4 (-59.6927, -11.51) -> (-84.1416, 23.066)
  line L5 (-110.9231, 23.066) -> (-59.6927, -11.51)
  line L6 (-84.1416, 23.066) -> (-110.9231, 23.066)
  point P1 (0, 0)
  point P2 (-82.0711, 27.066)
  point P3 (-43.7939, -27.066)
  point P4 (-124, 27.066)
  dimension "d360" distance P1 P2 = 82.0711 (= "Linear Dimension-2")
  dimension "d361" distance P1 P2 = 27.066 (= "Linear Dimension-3")
  dimension "d362" distance P1 P3 = 43.7939 (= "Linear Dimension-4")
  dimension "d363" distance P1 P3 = 27.066 (= "Linear Dimension-5")
  dimension "d364" distance P1 P4 = 124 (= "Linear Dimension-6")
  dimension "d365" distance P1 P4 = 27.066 (= "Linear Dimension-7")
  dimension "d366" = 4 (= "memberWidth / 2")
extrude "Extrude3" cut sketch "B Facet 45 Triangle 1" profile of L5 L6 L4 against normal blind 4.7 (magnitude of "-( wall + 0.2 mm )")
sketch "B Facet 45 Triangle 2" plane through (0, 53.033, 53.033) normal (0, 0.7071, 0.7071) x axis (1, 0, 0)
  line L1 (-124, 27.066) -> (-43.7939, -27.066)
  line L2 (-124, -27.066) -> (-124, 27.066)
  line L3 (-43.7939, -27.066) -> (-124, -27.066)
  line L4 (-120, 19.5406) -> (-56.8709, -23.066)
  line L5 (-120, -23.066) -> (-120, 19.5406)
  line L6 (-56.8709, -23.066) -> (-120, -23.066)
  point P1 (0, 0)
  point P2 (-43.7939, -27.066)
  point P3 (-124, 27.066)
  point P4 (-124, -27.066)
  dimension "d369" distance P1 P2 = 43.7939 (= "Linear Dimension-2")
  dimension "d370" distance P1 P2 = 27.066 (= "Linear Dimension-3")
  dimension "d371" distance P1 P3 = 124 (= "Linear Dimension-4")
  dimension "d372" distance P1 P3 = 27.066 (= "Linear Dimension-5")
  dimension "d373" distance P1 P4 = 124 (= "Linear Dimension-6")
  dimension "d374" distance P1 P4 = 27.066 (= "Linear Dimension-7")
  dimension "d375" = -4 (= "-memberWidth / 2")
extrude "Extrude4" cut sketch "B Facet 45 Triangle 2" profile of L5 L6 L4 against normal blind 4.7 (magnitude of "-( wall + 0.2 mm )")
fillet "Fillet2" radius 1.5 (= "apertureRadius")
work_plane "WorkPlane5" RotateAngle 0 ExtraOffset 0
work_plane "WorkPlane6" AlongDistance 75 (= "bodyWidth / 2") ExtraOffset 0
sketch "B Facet 90 Triangle 1" plane through (0, 0, 75) normal (0, 0, 1) x axis (1, 0, 0)
  line L1 (-36.9655, 27.066) -> (17.1665, -27.066)
  line L2 (-53.4167, -27.066) -> (-36.9655, 27.066)
  line L3 (17.1665, -27.066) -> (-53.4167, -27.066)
  line L4 (-35.0777, 19.5214) -> (7.5097, -23.066)
  line L5 (-48.0205, -23.066) -> (-35.0777, 19.5214)
  line L6 (7.5097, -23.066) -> (-48.0205, -23.066)
  point P1 (0, 0)
  point P2 (17.1665, -27.066)
  point P3 (-36.9655, 27.066)
  point P4 (-53.4167, -27.066)
  dimension "d384" distance P1 P2 = 17.1665 (= "Linear Dimension-2")
  dimension "d385" distance P1 P2 = 27.066 (= "Linear Dimension-3")
  dimension "d386" distance P1 P3 = 36.9655 (= "Linear Dimension-4")
  dimension "d387" distance P1 P3 = 27.066 (= "Linear Dimension-5")
  dimension "d388" distance P1 P4 = 53.4167 (= "Linear Dimension-6")
  dimension "d389" distance P1 P4 = 27.066 (= "Linear Dimension-7")
  dimension "d390" = -4 (= "-memberWidth / 2")
extrude "Extrude5" cut sketch "B Facet 90 Triangle 1" profile of L5 L6 L4 against normal blind 4.7 (magnitude of "-( wall + 0.2 mm )")
sketch "B Facet 90 Triangle 2" plane through (0, 0, 75) normal (0, 0, 1) x axis (1, 0, 0)
  line L1 (-53.4167, -27.066) -> (-36.9655, 27.066)
  line L2 (-124, 27.066) -> (-53.4167, -27.066)
  line L3 (-36.9655, 27.066) -> (-124, 27.066)
  line L4 (-55.5648, -20.3777) -> (-42.3618, 23.066)
  line L5 (-112.2115, 23.066) -> (-55.5648, -20.3777)
  line L6 (-42.3618, 23.066) -> (-112.2115, 23.066)
  point P1 (0, 0)
  point P2 (-36.9655, 27.066)
  point P3 (-53.4167, -27.066)
  point P4 (-124, 27.066)
  dimension "d393" distance P1 P2 = 36.9655 (= "Linear Dimension-2")
  dimension "d394" distance P1 P2 = 27.066 (= "Linear Dimension-3")
  dimension "d395" distance P1 P3 = 53.4167 (= "Linear Dimension-4")
  dimension "d396" distance P1 P3 = 27.066 (= "Linear Dimension-5")
  dimension "d397" distance P1 P4 = 124 (= "Linear Dimension-6")
  dimension "d398" distance P1 P4 = 27.066 (= "Linear Dimension-7")
  dimension "d399" = 4 (= "memberWidth / 2")
extrude "Extrude6" cut sketch "B Facet 90 Triangle 2" profile of L5 L6 L4 against normal blind 4.7 (magnitude of "-( wall + 0.2 mm )")
sketch "B Facet 90 Triangle 3" plane through (0, 0, 75) normal (0, 0, 1) x axis (1, 0, 0)
  line L1 (-124, 27.066) -> (-53.4167, -27.066)
  line L2 (-124, -27.066) -> (-124, 27.066)
  line L3 (-53.4167, -27.066) -> (-124, -27.066)
  line L4 (-120, 18.9574) -> (-65.2053, -23.066)
  line L5 (-120, -23.066) -> (-120, 18.9574)
  line L6 (-65.2053, -23.066) -> (-120, -23.066)
  point P1 (0, 0)
  point P2 (-53.4167, -27.066)
  point P3 (-124, 27.066)
  point P4 (-124, -27.066)
  dimension "d402" distance P1 P2 = 53.4167 (= "Linear Dimension-2")
  dimension "d403" distance P1 P2 = 27.066 (= "Linear Dimension-3")
  dimension "d404" distance P1 P3 = 124 (= "Linear Dimension-4")
  dimension "d405" distance P1 P3 = 27.066 (= "Linear Dimension-5")
  dimension "d406" distance P1 P4 = 124 (= "Linear Dimension-6")
  dimension "d407" distance P1 P4 = 27.066 (= "Linear Dimension-7")
  dimension "d408" = -4 (= "-memberWidth / 2")
extrude "Extrude7" cut sketch "B Facet 90 Triangle 3" profile of L5 L6 L4 against normal blind 4.7 (magnitude of "-( wall + 0.2 mm )")
fillet "Fillet3" radius 1.5 (= "apertureRadius")
work_plane "WorkPlane7" RotateAngle 45 ExtraOffset 0
work_plane "WorkPlane8" AlongDistance 75 (= "bodyWidth / 2") ExtraOffset 0
sketch "B Facet 135 Triangle 1" plane through (0, -53.033, 53.033) normal (0, -0.7071, 0.7071) x axis (1, 0, 0)
  line L1 (62.2721, -27.066) -> (23.9949, 27.066)
  line L2 (-25.3367, 27.066) -> (62.2721, -27.066)
  line L3 (23.9949, 27.066) -> (-25.3367, 27.066)
  line L4 (47.6674, -13.34) -> (21.9244, 23.066)
  line L5 (-11.2532, 23.066) -> (47.6674, -13.34)
  line L6 (21.9244, 23.066) -> (-11.2532, 23.066)
  point P1 (0, 0)
  point P2 (23.9949, 27.066)
  point P3 (62.2721, -27.066)
  point P4 (-25.3367, 27.066)
  dimension "d417" distance P1 P2 = 23.9949 (= "Linear Dimension-2")
  dimension "d418" distance P1 P2 = 27.066 (= "Linear Dimension-3")
  dimension "d419" distance P1 P3 = 62.2721 (= "Linear Dimension-4")
  dimension "d420" distance P1 P3 = 27.066 (= "Linear Dimension-5")
  dimension "d421" distance P1 P4 = 25.3367 (= "Linear Dimension-6")
  dimension "d422" distance P1 P4 = 27.066 (= "Linear Dimension-7")
  dimension "d423" = 4 (= "memberWidth / 2")
extrude "Extrude8" cut sketch "B Facet 135 Triangle 1" profile of L5 L6 L4 against normal blind 4.7 (magnitude of "-( wall + 0.2 mm )")
sketch "B Facet 135 Triangle 2" plane through (0, -53.033, 53.033) normal (0, -0.7071, 0.7071) x axis (1, 0, 0)
  line L1 (-25.3367, 27.066) -> (62.2721, -27.066)
  line L2 (-61.9093, -27.066) -> (-25.3367, 27.066)
  line L3 (62.2721, -27.066) -> (-61.9093, -27.066)
  line L4 (-24.1722, 21.6445) -> (48.1886, -23.066)
  line L5 (-54.3795, -23.066) -> (-24.1722, 21.6445)
  line L6 (48.1886, -23.066) -> (-54.3795, -23.066)
  point P1 (0, 0)
  point P2 (62.2721, -27.066)
  point P3 (-25.3367, 27.066)
  point P4 (-61.9093, -27.066)
  dimension "d426" distance P1 P2 = 62.2721 (= "Linear Dimension-2")
  dimension "d427" distance P1 P2 = 27.066 (= "Linear Dimension-3")
  dimension "d428" distance P1 P3 = 25.3367 (= "Linear Dimension-4")
  dimension "d429" distance P1 P3 = 27.066 (= "Linear Dimension-5")
  dimension "d430" distance P1 P4 = 61.9093 (= "Linear Dimension-6")
  dimension "d431" distance P1 P4 = 27.066 (= "Linear Dimension-7")
  dimension "d432" = -4 (= "-memberWidth / 2")
extrude "Extrude9" cut sketch "B Facet 135 Triangle 2" profile of L5 L6 L4 against normal blind 4.7 (magnitude of "-( wall + 0.2 mm )")
sketch "B Facet 135 Triangle 3" plane through (0, -53.033, 53.033) normal (0, -0.7071, 0.7071) x axis (1, 0, 0)
  line L1 (-61.9093, -27.066) -> (-25.3367, 27.066)
  line L2 (-124, 27.066) -> (-61.9093, -27.066)
  line L3 (-25.3367, 27.066) -> (-124, 27.066)
  line L4 (-62.6909, -21.0779) -> (-32.8665, 23.066)
  line L5 (-113.325, 23.066) -> (-62.6909, -21.0779)
  line L6 (-32.8665, 23.066) -> (-113.325, 23.066)
  point P1 (0, 0)
  point P2 (-25.3367, 27.066)
  point P3 (-61.9093, -27.066)
  point P4 (-124, 27.066)
  dimension "d435" distance P1 P2 = 25.3367 (= "Linear Dimension-2")
  dimension "d436" distance P1 P2 = 27.066 (= "Linear Dimension-3")
  dimension "d437" distance P1 P3 = 61.9093 (= "Linear Dimension-4")
  dimension "d438" distance P1 P3 = 27.066 (= "Linear Dimension-5")
  dimension "d439" distance P1 P4 = 124 (= "Linear Dimension-6")
  dimension "d440" distance P1 P4 = 27.066 (= "Linear Dimension-7")
  dimension "d441" = 4 (= "memberWidth / 2")
extrude "Extrude10" cut sketch "B Facet 135 Triangle 3" profile of L5 L6 L4 against normal blind 4.7 (magnitude of "-( wall + 0.2 mm )")
sketch "B Facet 135 Triangle 4" plane through (0, -53.033, 53.033) normal (0, -0.7071, 0.7071) x axis (1, 0, 0)
  line L1 (-124, 27.066) -> (-61.9093, -27.066)
  line L2 (-124, -27.066) -> (-124, 27.066)
  line L3 (-61.9093, -27.066) -> (-124, -27.066)
  line L4 (-120, 18.272) -> (-72.5843, -23.066)
  line L5 (-120, -23.066) -> (-120, 18.272)
  line L6 (-72.5843, -23.066) -> (-120, -23.066)
  point P1 (0, 0)
  point P2 (-61.9093, -27.066)
  point P3 (-124, 27.066)
  point P4 (-124, -27.066)
  dimension "d444" distance P1 P2 = 61.9093 (= "Linear Dimension-2")
  dimension "d445" distance P1 P2 = 27.066 (= "Linear Dimension-3")
  dimension "d446" distance P1 P3 = 124 (= "Linear Dimension-4")
  dimension "d447" distance P1 P3 = 27.066 (= "Linear Dimension-5")
  dimension "d448" distance P1 P4 = 124 (= "Linear Dimension-6")
  dimension "d449" distance P1 P4 = 27.066 (= "Linear Dimension-7")
  dimension "d450" = -4 (= "-memberWidth / 2")
extrude "Extrude11" cut sketch "B Facet 135 Triangle 4" profile of L5 L6 L4 against normal blind 4.7 (magnitude of "-( wall + 0.2 mm )")
fillet "Fillet4" radius 1.5 (= "apertureRadius")
work_plane "WorkPlane9" RotateAngle 90 ExtraOffset 0
work_plane "WorkPlane10" AlongDistance 75 (= "bodyWidth / 2") ExtraOffset 0
sketch "B Facet 180 Triangle 1" plane through (0, -75, 0) normal (0, -1, 0) x axis (-1, 0, 0)
  line L1 (-65.1005, 27.066) -> (-65.1005, -27.066)
  line L2 (-2.067, -27.066) -> (-65.1005, 27.066)
  line L3 (-65.1005, -27.066) -> (-2.067, -27.066)
  line L4 (-61.1005, 18.3583) -> (-61.1005, -23.066)
  line L5 (-12.8644, -23.066) -> (-61.1005, 18.3583)
  line L6 (-61.1005, -23.066) -> (-12.8644, -23.066)
  point P1 (0, 0)
  point P2 (-65.1005, -27.066)
  point P3 (-65.1005, 27.066)
  point P4 (-2.067, -27.066)
  dimension "d459" distance P1 P2 = 65.1005 (= "Linear Dimension-2")
  dimension "d460" distance P1 P2 = 27.066 (= "Linear Dimension-3")
  dimension "d461" distance P1 P3 = 65.1005 (= "Linear Dimension-4")
  dimension "d462" distance P1 P3 = 27.066 (= "Linear Dimension-5")
  dimension "d463" distance P1 P4 = 2.067 (= "Linear Dimension-6")
  dimension "d464" distance P1 P4 = 27.066 (= "Linear Dimension-7")
  dimension "d465" = 4 (= "memberWidth / 2")
extrude "Extrude12" cut sketch "B Facet 180 Triangle 1" profile of L5 L6 L4 against normal blind 4.7 (magnitude of "-( wall + 0.2 mm )")
sketch "B Facet 180 Triangle 2" plane through (0, -75, 0) normal (0, -1, 0) x axis (-1, 0, 0)
  line L1 (-2.067, -27.066) -> (-65.1005, 27.066)
  line L2 (60.9665, 27.066) -> (-2.067, -27.066)
  line L3 (-65.1005, 27.066) -> (60.9665, 27.066)
  line L4 (-2.067, -21.7934) -> (-54.3031, 23.066)
  line L5 (50.1691, 23.066) -> (-2.067, -21.7934)
  line L6 (-54.3031, 23.066) -> (50.1691, 23.066)
  point P1 (0, 0)
  point P2 (-65.1005, 27.066)
  point P3 (-2.067, -27.066)
  point P4 (60.9665, 27.066)
  dimension "d468" distance P1 P2 = 65.1005 (= "Linear Dimension-2")
  dimension "d469" distance P1 P2 = 27.066 (= "Linear Dimension-3")
  dimension "d470" distance P1 P3 = 2.067 (= "Linear Dimension-4")
  dimension "d471" distance P1 P3 = 27.066 (= "Linear Dimension-5")
  dimension "d472" distance P1 P4 = 60.9665 (= "Linear Dimension-6")
  dimension "d473" distance P1 P4 = 27.066 (= "Linear Dimension-7")
  dimension "d474" = -4 (= "-memberWidth / 2")
extrude "Extrude13" cut sketch "B Facet 180 Triangle 2" profile of L5 L6 L4 against normal blind 4.7 (magnitude of "-( wall + 0.2 mm )")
